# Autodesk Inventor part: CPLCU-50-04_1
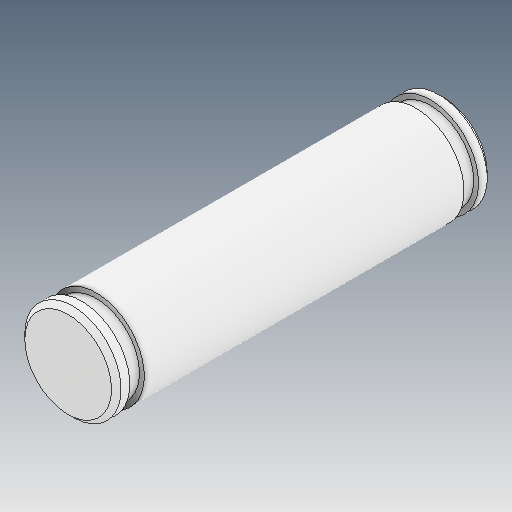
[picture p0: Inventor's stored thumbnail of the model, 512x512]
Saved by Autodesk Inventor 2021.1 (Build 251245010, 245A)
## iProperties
Created: 2021-06
Part Number: CPLCU-50-04_1
Material: Ogólny
Document SubType Name: Modeling
Designer: user
Density: 1 g/cm^3
Appearance: Domyślna
Author: user
Revision Number: ÈÎºÎ
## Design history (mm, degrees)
feature "ÊäÈë1"
node "Bryła1"
